(* Logix 5000 project; controller MVI56E_MNET 1756-L63 rev 18.11; software revision 18.02 *)

TASK MainTask (continuous, watchdog 500 ms) : MainProgram

MODULES
   Local : 1756-L63 (ICP 0, rev 18.11)
      MVI56E_MNET : vendor 1 type 0 code 15 (ICP 1, rev 1.1, Output RPI 5 ms)
END_MODULES

TYPE MNETBLKSTAT :   // This object is used to store the block transfer statistics for the MVI56-MNET module.
STRUCT
   Read : INT;   // Total number of read block transfers
   Write : INT;   // Total number of write block transfers
   Parse : INT;   // Total number of blocks parsed
   Event : INT;   // Total number of event blocks received
   Cmd : INT;   // Total number of command blocks received
   Err : INT;   // Total number of block transfer errors
END_STRUCT
END_TYPE

TYPE MNETCMDCONTROL :   // Controlling the Modbus Commands
STRUCT
   TriggerCmdCntrl : BOOL;   // Trigger Command Control. User application will activate this trigger.
   NumberOfCommands : INT;   // Number of commands per block (1 to 6)
   CommandIndex : INT[6];   // Stores the command indexes for command control.
   CmdsAddedToQueue : INT;   // Number of commands added to queue
   CmdControlBlockID : INT;   // Temporary variable to calculate control block ID
   CmdCntrlPending : BOOL;   // Auxiliary control command - prevents a second request before acknowledgment is received
END_STRUCT
END_TYPE

TYPE MNETCONTROL :   // Values used by program for data transfer operation between the module and the processor.
STRUCT
   WarmBoot : BOOL;   // Causes software reset. The Module reads new configuration information.
   ColdBoot : BOOL;   // Causes hardware reset.
   BPLastRead : INT;   // Index of last read block
   BPLastWrite : INT;   // Index of last write block
   BlockIndex : INT;   // Computed block offset for data table
   WBPending : BOOL;   // Pending message
   CBPending : BOOL;   // Pending message
   ReadDataBlkCount : INT;   // Holds the value of the Block Counts of the Read Data Array. Array Size is divided by 200.
   WriteDataBlkCount : INT;   // Holds the value of the Block Counts of the Write Data Array. Array Size is divided by 200.
   RBTSremainder : INT;   // Holds remainder calculation value from the read array.
   WBTSremainder : INT;   // Holds remainder calculation value from the write array.
   ReadDataSizeGet : INT;   // Holds read data array size.
   WriteDataSizeGet : INT;   // Holds write data array size.
   IPAddress : MNETIPADDRESS;   // Getting and Setting IP address to and from Module
   FaultCode : INT;   // Fault Code value
   CheckInitialization : BOOL;   // Check Initialization trigger
END_STRUCT
END_TYPE

TYPE MNETDATA :   // Contains Read Data (data read from the module to the processor) and Write Data (data written from the processor to the module)
STRUCT
   ReadData : INT[600];   // Data read from module. Set array equal to the size set in the Configuration file.
   WriteData : INT[600];   // Data to write to module. Set array equal to the size set in the Configuration file.
END_STRUCT
END_TYPE

TYPE MNETEVENTCMD :   // Data structure to use for Event message generation.
STRUCT
   EventCmdTrigger : BOOL;   // Trigger for event command. User ladder must set this bit to initiate event command
   EventCmdPending : BOOL;   // Set after the ladder has sent an event cmd to the module and is waiting for the status to be returned
   IPAddress : INT[4];   // Server IP address. example: 192.168.0.101
   ServicePort : INT;   // TCP Service Port number (0-65535), 502 for MBAP, 2000 for MNET
   SlaveAddress : INT;   // Modbus slave NODE address (0 to 247)
   InternalDBAddress : INT;   // Internal database address
   PointCount : INT;   // Number of points for this command
   SwapCode : INT;   // Swap code (0= no swap, 1=swap words, 2=swap words and bytes, 3=swap bytes)
   ModbusFunctionCode : INT;   // Modbus function code
   DeviceDBAddress : INT;   // Target Server Modbus Address.
   EventCmdStatusReturned : INT;   // (0=Fail, 1=Success)
   EventBlockID : INT;   // Temporary variable to calculate event block ID
END_STRUCT
END_TYPE

TYPE MNETINITOUTDATA :   // Used to bring the Module into a known state after a restart operation.
STRUCT
   TriggerInitOut : BOOL;   // Trigger Output Data Initialization.
   InitializeOutputData : INT;   // Quantity of Blocks(200 words of "ReadData") for the module to read from the PLC. [0 to 24] means a qty of 1 to 25
   RetInitOutData : INT[200];   // Returned Initialization output data
   TriggerInitOutPending : BOOL;   // Set after the ladder has sent an event cmd to the module and is waiting for the status to be returned
   RetInitOutDataBlkID : INT;   // Returned Block ID for Returned Initialize Output Data command.
   InitOutBlkIDLim : INT;   // Block Index Limit for ReadData size of the array
END_STRUCT
END_TYPE

TYPE MNETIPADDRESS :   // Data structure to get and set the IP address of the module.
STRUCT
   IPGetTrigger : BOOL;   // Gets IP address.
   IPReceived : INT[4];   // IP address received.
   IPSetTrigger : BOOL;   // Sets IP address
   IPRequested : INT[4];   // IP address set.
END_STRUCT
END_TYPE

TYPE MNETMODULEDEF :   // This defines the whole module which includes all tags used in the program
STRUCT
   DATA : MNETDATA;   // Data read from module
   STATUS : MNETSTATUS;   // Client ,Server Status and blocks status
   CONTROL : MNETCONTROL;   // MNET Module control warmboot, coldboot, etc
   UTIL : MNETUTIL;   // command, event control
END_STRUCT
END_TYPE

TYPE MNETPASSTHRU :   // Applicable with the selection of a Pass-Through mode (1 to 3) in the Configuration file.
STRUCT
   MBControl1 : CONTROL;   // Modbus pass thru message control
   MBControl2 : CONTROL;   // Modbus pass thru message control
   Mbdouble : DINT;   // Modbus double int tag
   MBMsg : SINT[500];   // Message array
   MBMsgLen : INT;   // Message length
   MBOffset : INT;   // Start offset in the message
   MBOffsetBit : INT;   // Offset bit in the message
   MBScratch : INT[3];   // Temporary used ints
   MBboolLength : DINT;   // Holds Word size that will accommodate Coil Qty.
   MBSpecial : INT[4];   // Holds Special Function 99 data.
   WriteDataDINTBuffer : DINT[50];   // Hold WriteData in DINT array
   InputDataDINTBuffer : DINT[50];   // Hold Connection Input Data in DINT array
END_STRUCT
END_TYPE

TYPE MNETSTATS :   // This object is used to store the port statistics for an MVI56-MNET port.
STRUCT
   CmdReq : INT;   // Total number of command list requests sent
   CmdResp : INT;   // Total number of command list responses received
   CmdErr : INT;   // Total number of command list errors
   Requests : INT;   // Total number of requests for port
   Responses : INT;   // Total number of responses for port
   ErrSent : INT;   // Total number of errors sent
   ErrRec : INT;   // Total number of errors received
   CfgErrWord : INT;   // Configuration Error Word
   CurErr : INT;   // Current Error code
   LastErr : INT;   // Last recorded error code
END_STRUCT
END_TYPE

TYPE MNETSTATUS :   // This status data is returned on each read block and can be used to detect proper module operation.
STRUCT
   PassCnt : INT;   // Program cycle counter
   ProductVersion : INT;   // Shows the module software version
   ProductCode : INT[2];   // This identifies the module product code
   MnetServStats : MNETSTATS;   // Server status for port 502
   MBAPServStats : MNETSTATS;   // Server status for port 2000
   ClientStats : MNETSTATS;   // Client Status
   BlockStats : MNETBLKSTAT;   // Block Transfer Statistics.
END_STRUCT
END_TYPE

TYPE MNETUTIL :   // Variables for internal ladder usage - should not be accessed by user application
STRUCT
   CmdControl : MNETCMDCONTROL;   // Allows for a disabled command to be sent to a device(Server)
   EventCmd : MNETEVENTCMD;   // Event data to be used
   InitOutputData : MNETINITOUTDATA;   // This is to initialize output data module reads data from PLC
   PassThru : MNETPASSTHRU;   // This is to handle the pass thru format to be passed straight to the processor.
   IPsetPending : BOOL;   // Allows Setting module IP address
   IPgetPending : BOOL;   // Allows Getting module IP address
END_STRUCT
END_TYPE

ADD_ON_INSTRUCTION AOI56MNET   (* revision 1.62, vendor ProSoft Technology Inc., ExecutePrescan *)
// Add-On - MVI56-MNET and  MVI56E-MNET modules.
// Revision note:
// v1.62. resolves minor arithmetic overflow fault when msb of WriteData registers are set during a function 5 or 15 while passthru
VAR_IN_OUT
   Connection_Input : INT[250]; {required}   // Input parameters.
   Connection_Output : INT[248]; {required}   // Output parameters.
   MNET : MNETMODULEDEF; {required}
        .DATA.READDATA[0]   // Reads the RadData array size.
        ._UTIL.PASSTHRU.MBMSG[0]   // Modbus reserved. Always 0.
        ._UTIL.PASSTHRU.MBMSG[3]   // Modbus Function Code received.
        ._UTIL.PASSTHRU.MBOFFSET   // Starting Address for Modbus data set.
END_VAR
VAR
   MJFAULTS : DINT[12];
END_VAR

ROUTINE Logic   (* ladder *)
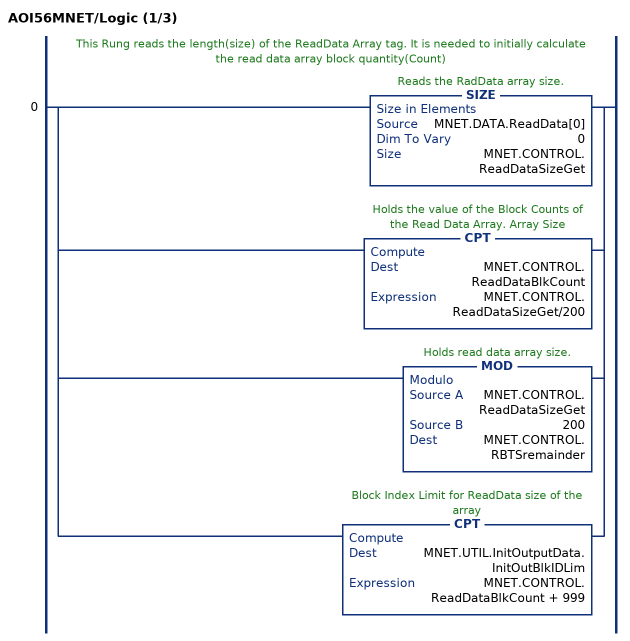
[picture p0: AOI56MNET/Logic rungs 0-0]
   // This Rung reads the length(size) of the ReadData Array tag. It is needed to initially calculate the read data array block quantity(Count)
   0: [SIZE(MNET.DATA.ReadData[0],0,MNET.CONTROL.ReadDataSizeGet) ,CPT(MNET.CONTROL.ReadDataBlkCount,MNET.CONTROL.ReadDataSizeGet/200) ,MOD(MNET.CONTROL.ReadDataSizeGet,200,MNET.CONTROL.RBTSremainder) ,CPT(MNET.UTIL.InitOutputData.InitOutBlkIDLim,MNET.CONTROL.ReadDataBlkCount + 999) ];
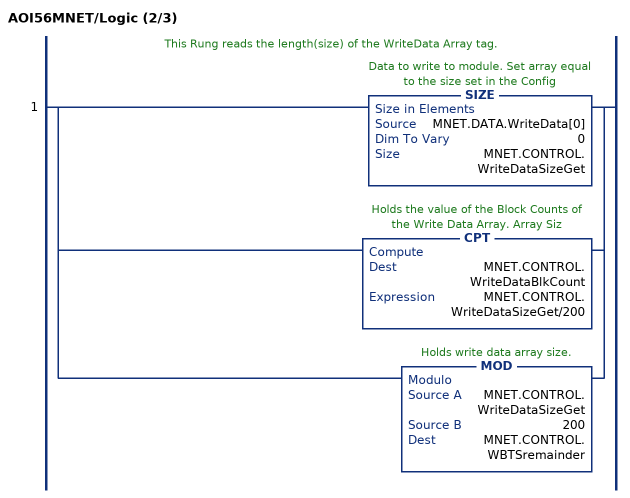
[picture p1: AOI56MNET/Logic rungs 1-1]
   // This Rung reads the length(size) of the WriteData Array tag.
   1: [SIZE(MNET.DATA.WriteData[0],0,MNET.CONTROL.WriteDataSizeGet) ,CPT(MNET.CONTROL.WriteDataBlkCount,MNET.CONTROL.WriteDataSizeGet/200) ,MOD(MNET.CONTROL.WriteDataSizeGet,200,MNET.CONTROL.WBTSremainder) ];
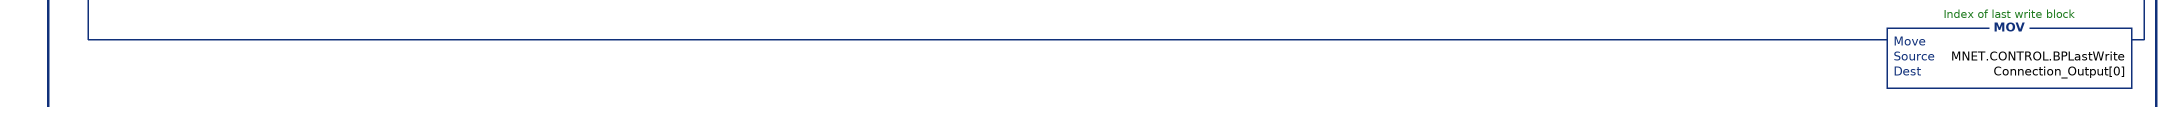
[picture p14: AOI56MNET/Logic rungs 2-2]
   // This rung is used to check for a new read block from the MVI56-MNET module in slot 1.  If new data is available, the LastRead and word[0] will not be equal.  This will force the program to call the ReadData subroutine to process the new data received.  After the new data is placed in the Modbus Data Table, the program will send new data to the module using the WriteData subroutine.
   2: NEQ(Connection_Input[249],MNET.CONTROL.BPLastRead)[MOV(Connection_Input[249],MNET.CONTROL.BPLastRead) ,GRT(MNET.CONTROL.FaultCode,0) OTL(MNET.CONTROL.CheckInitialization) ,EQU(MNET.CONTROL.FaultCode,0) NEQ(MNET.CONTROL.FaultCode,0) OTU(MNET.CONTROL.CheckInitialization) ,EQU(MNET.CONTROL.FaultCode,0) [EQU(-1,MNET.CONTROL.BPLastRead) ,EQU(0,MNET.CONTROL.BPLastRead) ] XIO(MNET.CONTROL.CheckInitialization) [[EQU(MNET.STATUS.ProductCode[1],13637) GEQ(MNET.STATUS.ProductVersion,205) ,EQU(MNET.STATUS.ProductCode[1],13652) GEQ(MNET.STATUS.ProductVersion,151) ] [GEQ(MNET.CONTROL.ReadDataSizeGet,200) COP(Connection_Input[2],MNET.DATA.ReadData[0],200) ,LES(MNET.CONTROL.ReadDataSizeGet,200) COP(Connection_Input[2],MNET.DATA.ReadData[0],MNET.CONTROL.RBTSremainder) ] ,COP(Connection_Input[202],MNET.STATUS.PassCnt,1) ,COP(Connection_Input[203],MNET.STATUS.BlockStats.Read,6) ,COP(Connection_Input[209],MNET.STATUS.ProductCode[0],2) ,COP(Connection_Input[211],MNET.STATUS.ProductVersion,1) ,COP(Connection_Input[219],MNET.STATUS.MnetServStats.CmdReq,10) ,COP(Connection_Input[229],MNET.STATUS.MBAPServStats.CmdReq,10) ,COP(Connection_Input[239],MNET.STATUS.ClientStats.CmdReq,10) ] ,GEQ(MNET.CONTROL.BPLastRead,1) [LEQ(MNET.CONTROL.BPLastRead,MNET.CONTROL.ReadDataBlkCount) [CPT(MNET.CONTROL.BlockIndex,(MNET.CONTROL.BPLastRead-1)*200) ,COP(Connection_Input[2],MNET.DATA.ReadData[MNET.CONTROL.BlockIndex],200) ] ,CMP(MNET.CONTROL.BPLastRead - MNET.CONTROL.ReadDataBlkCount = 1) GRT(MNET.CONTROL.RBTSremainder,0) [CPT(MNET.CONTROL.BlockIndex,(MNET.CONTROL.BPLastRead-1)*200) ,COP(Connection_Input[2],MNET.DATA.ReadData[MNET.CONTROL.BlockIndex],MNET.CONTROL.RBTSremainder) ] ,LEQ(MNET.CONTROL.BPLastRead,25) [MOV(Connection_Input[202],MNET.STATUS.PassCnt) ,COP(Connection_Input[203],MNET.STATUS.BlockStats.Read,6) ,COP(Connection_Input[209],MNET.STATUS.ProductCode[0],2) ,COP(Connection_Input[211],MNET.STATUS.ProductVersion,1) ,COP(Connection_Input[219],MNET.STATUS.MnetServStats.CmdReq,10) ,COP(Connection_Input[229],MNET.STATUS.MBAPServStats.CmdReq,10) ,COP(Connection_Input[239],MNET.STATUS.ClientStats.CmdReq,10) ] ] ,EQU(MNET.CONTROL.BPLastRead,9990) [COP(Connection_Input[2],MNET.CONTROL.IPAddress.IPRequested[0],4) ,OTU(MNET.UTIL.IPsetPending) ] ,EQU(MNET.CONTROL.BPLastRead,9991) [COP(Connection_Input[2],MNET.CONTROL.IPAddress.IPReceived[0],4) ,OTU(MNET.UTIL.IPgetPending) ] ,LIM(9956,MNET.CONTROL.BPLastRead,9996) [EQU(9996,MNET.CONTROL.BPLastRead) [MOV(Connection_Input[2],MNET.UTIL.PassThru.MBMsgLen) ,COP(Connection_Input[3],MNET.UTIL.PassThru.MBMsg[0],MNET.UTIL.PassThru.MBMsgLen) ] ,LIM(9956,MNET.CONTROL.BPLastRead,9957) [MOV(Connection_Input[3],MNET.UTIL.PassThru.MBOffset) ,LES(MNET.UTIL.PassThru.MBOffset,MNET.CONTROL.WriteDataSizeGet) COP(Connection_Input[4],MNET.DATA.WriteData[MNET.UTIL.PassThru.MBOffset],Connection_Input[2]) ] ,EQU(9958,MNET.CONTROL.BPLastRead) [MOV(Connection_Input[3],MNET.UTIL.PassThru.MBOffsetBit) ,MOV(Connection_Input[4],MNET.UTIL.PassThru.MBScratch[2]) ,DIV(MNET.UTIL.PassThru.MBOffsetBit,16,MNET.UTIL.PassThru.MBOffset) ,MOD(MNET.UTIL.PassThru.MBOffsetBit,16,MNET.UTIL.PassThru.MBOffsetBit) ,XPY(2,MNET.UTIL.PassThru.MBOffsetBit,MNET.UTIL.PassThru.mbdouble) ,MVM(MNET.UTIL.PassThru.mbdouble,16#0000_ffff,MNET.UTIL.PassThru.MBOffsetBit) ,COP(MNET.DATA.WriteData[MNET.UTIL.PassThru.MBOffset],MNET.UTIL.PassThru.WriteDataDINTBuffer[0],1) ,GEQ(MNET.UTIL.PassThru.MBOffset,0) LES(MNET.UTIL.PassThru.MBOffset,MNET.CONTROL.WriteDataSizeGet) LEQ(MNET.UTIL.PassThru.MBOffset,2048) [NEQ(MNET.UTIL.PassThru.MBScratch[2],0) OR(MNET.UTIL.PassThru.MBOffsetBit,MNET.DATA.WriteData[MNET.UTIL.PassThru.MBOffset],MNET.UTIL.PassThru.WriteDataDINTBuffer[0]) ,EQU(MNET.UTIL.PassThru.MBScratch[2],0) [NOT(MNET.UTIL.PassThru.MBOffsetBit,MNET.UTIL.PassThru.MBOffsetBit) ,AND(MNET.UTIL.PassThru.MBOffsetBit,MNET.DATA.WriteData[MNET.UTIL.PassThru.MBOffset],MNET.UTIL.PassThru.WriteDataDINTBuffer[0]) ] ,COP(MNET.UTIL.PassThru.WriteDataDINTBuffer[0],MNET.DATA.WriteData[MNET.UTIL.PassThru.MBOffset],1) ] ] ,EQU(9959,MNET.CONTROL.BPLastRead) [[MOV(Connection_Input[3],MNET.UTIL.PassThru.MBOffset) ,CPT(MNET.UTIL.PassThru.MBControl1.LEN,Connection_Input[2]/2+(Connection_Input[2] MOD 2)) MOV(MNET.UTIL.PassThru.MBControl1.LEN,MNET.UTIL.PassThru.MBControl2.LEN) ,CPT(MNET.UTIL.PassThru.MBboolLength,MNET.UTIL.PassThru.MBOffset+Connection_Input[2]) ,COP(Connection_Input[4],MNET.UTIL.PassThru.InputDataDINTBuffer[0],50) ,COP(MNET.DATA.WriteData[MNET.UTIL.PassThru.MBOffset],MNET.UTIL.PassThru.WriteDataDINTBuffer[0],MNET.UTIL.PassThru.MBControl1.LEN) ] ,LEQ(MNET.UTIL.PassThru.MBboolLength,MNET.CONTROL.WriteDataSizeGet) [FAL(MNET.UTIL.PassThru.MBControl1,?,?,ALL,MNET.UTIL.PassThru.WriteDataDINTBuffer[MNET.UTIL.PassThru.MBControl1.POS],MNET.UTIL.PassThru.WriteDataDINTBuffer[MNET.UTIL.PassThru.MBControl1.POS] AND(NOT MNET.UTIL.PassThru.InputDataDINTBuffer[25+MNET.UTIL.PassThru.MBControl1.POS])) ,FAL(MNET.UTIL.PassThru.MBControl2,?,?,ALL,MNET.UTIL.PassThru.WriteDataDINTBuffer[MNET.UTIL.PassThru.MBControl2.POS],MNET.UTIL.PassThru.WriteDataDINTBuffer[MNET.UTIL.PassThru.MBControl2.POS] OR(MNET.UTIL.PassThru.InputDataDINTBuffer[25+MNET.UTIL.PassThru.MBControl2.POS] AND MNET.UTIL.PassThru.InputDataDINTBuffer[MNET.UTIL.PassThru.MBControl2.POS])) ,RES(MNET.UTIL.PassThru.MBControl1) ,RES(MNET.UTIL.PassThru.MBControl2) ,COP(MNET.UTIL.PassThru.WriteDataDINTBuffer[0],MNET.DATA.WriteData[MNET.UTIL.PassThru.MBOffset],Connection_Input[2]) ] ] ,LIM(9960,MNET.CONTROL.BPLastRead,9961) [MOV(Connection_Input[3],MNET.UTIL.PassThru.MBOffset) ,MOV(Connection_Input[2],MNET.UTIL.PassThru.MBMsgLen) ,COP(Connection_Input[4],MNET.DATA.WriteData[MNET.UTIL.PassThru.MBOffset],MNET.UTIL.PassThru.MBMsgLen) ,CPT(MNET.UTIL.PassThru.MBMsgLen,MNET.UTIL.PassThru.MBMsgLen*2+2) ,COP(Connection_Input[3],MNET.UTIL.PassThru.MBMsg[0],MNET.UTIL.PassThru.MBMsgLen) ] ,EQU(9970,MNET.CONTROL.BPLastRead) COP(Connection_Output[0],MNET.UTIL.PassThru.MBSpecial[0],4) ] ,LIM(5001,MNET.CONTROL.BPLastRead,5006) [MOV(MNET.CONTROL.BPLastRead,MNET.UTIL.CmdControl.CmdControlBlockID) ,MOV(Connection_Input[2],MNET.UTIL.CmdControl.CmdsAddedToQueue) ,OTU(MNET.UTIL.CmdControl.CmdCntrlPending) ,OTU(MNET.UTIL.CmdControl.TriggerCmdCntrl) ] ,EQU(MNET.CONTROL.BPLastRead,2000) [MOV(MNET.CONTROL.BPLastRead,MNET.UTIL.EventCmd.EventBlockID) ,MOV(Connection_Input[2],MNET.UTIL.EventCmd.EventCmdStatusReturned) ,OTU(MNET.UTIL.EventCmd.EventCmdPending) ,OTU(MNET.UTIL.EventCmd.EventCmdTrigger) ] ,MOV(Connection_Input[1],MNET.CONTROL.BPLastWrite) ,XIC(MNET.CONTROL.WarmBoot) [MOV(9998,MNET.CONTROL.BPLastWrite) ,OTU(MNET.CONTROL.WarmBoot) ] ,XIC(MNET.CONTROL.ColdBoot) [MOV(9999,MNET.CONTROL.BPLastWrite) ,OTU(MNET.CONTROL.ColdBoot) ] ,[EQU(-1,MNET.CONTROL.BPLastWrite) ,EQU(0,MNET.CONTROL.BPLastWrite) ] [EQU(MNET.STATUS.ProductCode[1],13637) GEQ(MNET.STATUS.ProductVersion,205) ,EQU(MNET.STATUS.ProductCode[1],13652) GEQ(MNET.STATUS.ProductVersion,151) ] [GEQ(MNET.CONTROL.WriteDataSizeGet,200) COP(MNET.DATA.WriteData[0],Connection_Output[1],200) ,LES(MNET.CONTROL.WriteDataSizeGet,200) COP(MNET.DATA.WriteData[0],Connection_Output[1],MNET.CONTROL.WBTSremainder) ] ,GEQ(MNET.CONTROL.BPLastWrite,1) [LEQ(MNET.CONTROL.BPLastWrite,MNET.CONTROL.WriteDataBlkCount) [CPT(MNET.CONTROL.BlockIndex,(MNET.CONTROL.BPLastWrite-1)*200) ,COP(MNET.DATA.WriteData[MNET.CONTROL.BlockIndex],Connection_Output[1],200) ] ,CMP(MNET.CONTROL.BPLastWrite - MNET.CONTROL.WriteDataBlkCount = 1) GRT(MNET.CONTROL.WBTSremainder,0) [CPT(MNET.CONTROL.BlockIndex,(MNET.CONTROL.BPLastWrite-1)*200) ,COP(MNET.DATA.WriteData[MNET.CONTROL.BlockIndex],Connection_Output[1],MNET.CONTROL.WBTSremainder) ] ] ,LIM(1000,MNET.CONTROL.BPLastWrite,1024) LEQ(MNET.CONTROL.BPLastWrite,MNET.UTIL.InitOutputData.InitOutBlkIDLim) [CPT(MNET.CONTROL.BlockIndex,(MNET.CONTROL.BPLastWrite-1000)*200) ,COP(MNET.DATA.ReadData[MNET.CONTROL.BlockIndex],Connection_Output[1],200) ] ,XIC(MNET.CONTROL.IPAddress.IPSetTrigger) XIO(MNET.UTIL.IPsetPending) [COP(MNET.CONTROL.IPAddress.IPRequested[0],Connection_Output[1],4) ,MOV(9990,MNET.CONTROL.BPLastWrite) ,OTU(MNET.CONTROL.IPAddress.IPSetTrigger) ,OTL(MNET.UTIL.IPsetPending) ] ,XIC(MNET.CONTROL.IPAddress.IPGetTrigger) XIO(MNET.UTIL.IPgetPending) [MOV(9991,MNET.CONTROL.BPLastWrite) ,OTU(MNET.CONTROL.IPAddress.IPGetTrigger) ,OTL(MNET.UTIL.IPgetPending) ] ,XIC(MNET.UTIL.CmdControl.TriggerCmdCntrl) XIO(MNET.UTIL.CmdControl.CmdCntrlPending) [COP(MNET.UTIL.CmdControl.CommandIndex[0],Connection_Output[1],6) ,LIM(1,MNET.UTIL.CmdControl.NumberOfCommands,6) ADD(5000,MNET.UTIL.CmdControl.NumberOfCommands,MNET.CONTROL.BPLastWrite) ,OTL(MNET.UTIL.CmdControl.CmdCntrlPending) ] ,XIC(MNET.UTIL.EventCmd.EventCmdTrigger) XIO(MNET.UTIL.EventCmd.EventCmdPending) [MOV(2000,MNET.CONTROL.BPLastWrite) ,COP(MNET.UTIL.EventCmd.IPAddress[0],Connection_Output[1],11) ,OTL(MNET.UTIL.EventCmd.EventCmdPending) ] ,MOV(MNET.CONTROL.BPLastWrite,Connection_Output[0]) ];
END_ROUTINE

ROUTINE Prescan   (* ladder *)
// Startup
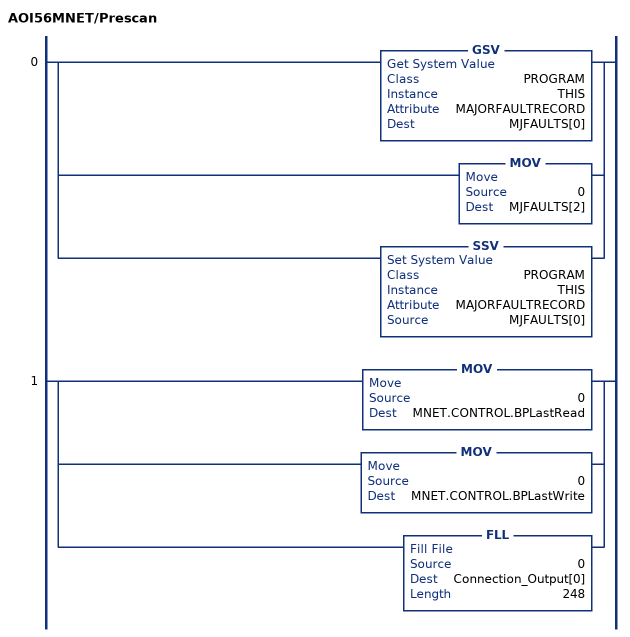
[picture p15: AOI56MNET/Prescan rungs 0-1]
   0: [GSV(PROGRAM,THIS,MAJORFAULTRECORD,MJFAULTS[0]) ,MOV(0,MJFAULTS[2]) ,SSV(PROGRAM,THIS,MAJORFAULTRECORD,MJFAULTS[0]) ];
   1: [MOV(0,MNET.CONTROL.BPLastRead) ,MOV(0,MNET.CONTROL.BPLastWrite) ,FLL(0,Connection_Output[0],248) ];
END_ROUTINE
END_ADD_ON_INSTRUCTION

VAR_GLOBAL   (* controller tags *)
   AOI56MNET : AOI56MNET;
   MNET : MNETMODULEDEF;   // Output parameters.
        .DATA.READDATA[0]   // Reads the ReadData array size.
        ._UTIL.PASSTHRU.MBMSG[0]   // Modbus reserved. Always 0.
        ._UTIL.PASSTHRU.MBMSG[3]   // Modbus Function Code received.
        ._UTIL.PASSTHRU.MBOFFSET   // Starting Address for Modbus data set.
END_VAR

PROGRAM MainProgram   (* main routine MainRoutine *)

ROUTINE MainRoutine   (* ladder *)
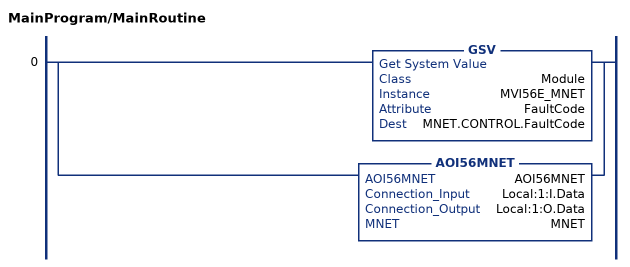
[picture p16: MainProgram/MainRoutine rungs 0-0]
   0: [GSV(Module,MVI56E_MNET,FaultCode,MNET.CONTROL.FaultCode) ,AOI56MNET(AOI56MNET,Local:1:I.Data,Local:1:O.Data,MNET) ];
END_ROUTINE
END_PROGRAM
